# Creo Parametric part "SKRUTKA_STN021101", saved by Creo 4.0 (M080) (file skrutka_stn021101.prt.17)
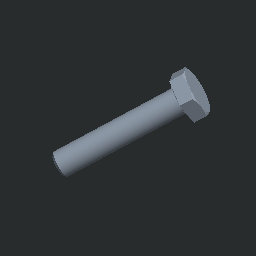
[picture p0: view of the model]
Units: Custom; MM, KILOGRAM, SECS
Materials in the file: OCEL_N

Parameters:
  KATEGORIE = "4"
  NAZOV = "SKRUTKA_STN021101"
  NORMA = "STN 02 1101"
  N2 = "21"
  N3 = "1"
  NAZOV_1 = "START_PART_IPM"
  PTC_MATERIAL_NAME = "OCEL_N"
  PLACEMENT = "A"

Other parameters: PB, HMOTNOST, HUSTOTA, HMOTNOST_1, THREADS_PER_INCH, D42, D2, D7, D25, D30, D1, D41

Created from: STN_021101_SKRUTKA_6HR.PRT

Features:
  1. chamfer
  2. datum plane "DTM1"
  3. protrusion
  4. datum plane "DTM6"
  5. cut
  6. datum plane "DTM7"
  7. cut
  8. datum plane "DTM8"
  9. datum plane "DTM9"

Layers: BEZUGSEBENEN, NORMTEILE

Family table entries: GENERIC, SKRUTKA_M3X16, SKRUTKA_STN021101, value(d_val), 2/0, 2/(, value(i_val), SKRUTKA_M3X20, SKRUTKA_STN021101, 2/4, 2/(, SKRUTKA_M3X25, SKRUTKA_STN021101, 2/9, 2/(, SKRUTKA_M4X25, SKRUTKA_STN021101, 2/9, 2/,, SKRUTKA_M4X30, SKRUTKA_STN021101, 2/>, 2/,, SKRUTKA_M4X35, SKRUTKA_STN021101, 2/,, SKRUTKA_M4X40, SKRUTKA_STN021101, 2/D, 2/,, SKRUTKA_M5X25, SKRUTKA_STN021101, 2/9, 2/ , 2/0, SKRUTKA_M5X30, SKRUTKA_STN021101, 2/>, 2/ , 2/0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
